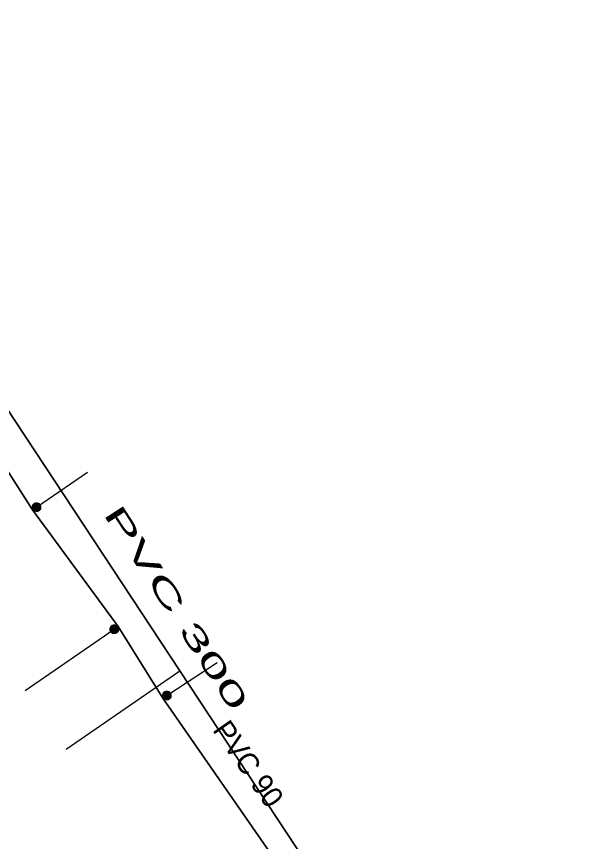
# Model space of a CAD drawing. Extents: x -873619 to -867639, y -1015082 to -1012326.
# Drawn here: x -867939.32 to -867910.18, y -1012859.98 to -1012817 of the extents above; entities that cross this region are included whole.
import ezdxf

# ---------------------------------------------------------------- set-up
doc = ezdxf.new("R2010")
doc.units = 0
doc.header["$LTSCALE"] = 0.44
for name, color, linetype, lineweight in [('1', 7, 'Continuous', 13), ('12', 7, 'Continuous', 13), ('21', 7, 'Continuous', 35), ('23', 7, 'Continuous', 25), ('3', 7, 'Continuous', 25)]:
    doc.layers.add(name, color=color, linetype=linetype, lineweight=lineweight)

msp = doc.modelspace()

# ---------------------------------------------------------------- linework, layer by layer
at = {"layer": '1', "lineweight": 35}
msp.add_lwpolyline([(-867979.181, -1012799.683), (-867972.83, -1012801.89), (-867965.59, -1012804.78), (-867963.787, -1012807.409), (-867948.768, -1012827.087), (-867948.538, -1012827.407), (-867943.513, -1012834.828), (-867938.476, -1012842.701), (-867934.013, -1012848.778), (-867931.689, -1012852.506), (-867924.702, -1012862.569), (-867923.496, -1012864.901), (-867916.531, -1012874.592), (-867908.231, -1012887.091), (-867905.717, -1012890.99), (-867899.122, -1012900.29), (-867892.55, -1012910.082), (-867889.71, -1012914.412), (-867888.18, -1012916.7), (-867891.84, -1012919), (-867886.89, -1012927.31), (-867886.728, -1012931.158)], dxfattribs=at)
at = {"layer": '12'}
for points in [[(-867938.039, -1012842.56), (-867938.045, -1012842.508), (-867938.062, -1012842.458), (-867938.091, -1012842.414), (-867938.128, -1012842.377), (-867938.173, -1012842.35), (-867938.223, -1012842.333), (-867938.276, -1012842.329), (-867938.328, -1012842.336), (-867938.377, -1012842.355), (-867938.42, -1012842.384), (-867938.456, -1012842.423), (-867938.482, -1012842.468), (-867938.498, -1012842.519), (-867938.501, -1012842.571), (-867938.493, -1012842.623), (-867938.473, -1012842.672), (-867938.442, -1012842.715), (-867938.403, -1012842.749), (-867938.357, -1012842.775), (-867938.306, -1012842.789), (-867938.253, -1012842.791), (-867938.202, -1012842.781), (-867938.154, -1012842.76), (-867938.111, -1012842.729), (-867938.077, -1012842.688), (-867938.053, -1012842.642), (-867938.041, -1012842.591)], [(-867938.069, -1012842.56), (-867938.075, -1012842.511), (-867938.092, -1012842.465), (-867938.12, -1012842.425), (-867938.157, -1012842.393), (-867938.201, -1012842.371), (-867938.249, -1012842.36), (-867938.298, -1012842.36), (-867938.345, -1012842.373), (-867938.388, -1012842.397), (-867938.424, -1012842.43), (-867938.451, -1012842.471), (-867938.467, -1012842.518), (-867938.471, -1012842.567), (-867938.464, -1012842.615), (-867938.445, -1012842.66), (-867938.415, -1012842.7), (-867938.377, -1012842.731), (-867938.333, -1012842.751), (-867938.285, -1012842.761), (-867938.236, -1012842.759), (-867938.189, -1012842.744), (-867938.146, -1012842.719), (-867938.112, -1012842.685), (-867938.086, -1012842.643), (-867938.072, -1012842.596)], [(-867938.099, -1012842.56), (-867938.105, -1012842.515), (-867938.122, -1012842.473), (-867938.15, -1012842.438), (-867938.186, -1012842.411), (-867938.228, -1012842.394), (-867938.273, -1012842.389), (-867938.318, -1012842.395), (-867938.359, -1012842.414), (-867938.394, -1012842.442), (-867938.421, -1012842.479), (-867938.437, -1012842.521), (-867938.441, -1012842.566), (-867938.434, -1012842.611), (-867938.415, -1012842.652), (-867938.386, -1012842.686), (-867938.349, -1012842.712), (-867938.306, -1012842.728), (-867938.261, -1012842.731), (-867938.216, -1012842.723), (-867938.176, -1012842.703), (-867938.142, -1012842.674), (-867938.116, -1012842.636), (-867938.102, -1012842.593)], [(-867938.129, -1012842.56), (-867938.134, -1012842.519), (-867938.152, -1012842.482), (-867938.179, -1012842.451), (-867938.214, -1012842.43), (-867938.254, -1012842.419), (-867938.295, -1012842.421), (-867938.334, -1012842.434), (-867938.368, -1012842.458), (-867938.393, -1012842.49), (-867938.408, -1012842.528), (-867938.411, -1012842.569), (-867938.403, -1012842.609), (-867938.383, -1012842.645), (-867938.354, -1012842.674), (-867938.317, -1012842.693), (-867938.277, -1012842.701), (-867938.236, -1012842.697), (-867938.198, -1012842.682), (-867938.166, -1012842.656), (-867938.143, -1012842.622), (-867938.13, -1012842.583)], [(-867938.159, -1012842.56), (-867938.164, -1012842.524), (-867938.182, -1012842.492), (-867938.208, -1012842.467), (-867938.242, -1012842.452), (-867938.278, -1012842.449), (-867938.313, -1012842.457), (-867938.344, -1012842.477), (-867938.367, -1012842.505), (-867938.38, -1012842.539), (-867938.38, -1012842.576), (-867938.369, -1012842.611), (-867938.348, -1012842.64), (-867938.318, -1012842.661), (-867938.283, -1012842.671), (-867938.246, -1012842.669), (-867938.212, -1012842.655), (-867938.185, -1012842.632), (-867938.166, -1012842.6), (-867938.159, -1012842.565)], [(-867938.189, -1012842.56), (-867938.194, -1012842.529), (-867938.211, -1012842.503), (-867938.237, -1012842.486), (-867938.267, -1012842.479), (-867938.298, -1012842.483), (-867938.325, -1012842.5), (-867938.343, -1012842.524), (-867938.351, -1012842.555), (-867938.347, -1012842.585), (-867938.332, -1012842.613), (-867938.308, -1012842.632), (-867938.278, -1012842.641), (-867938.247, -1012842.638), (-867938.219, -1012842.624), (-867938.199, -1012842.6), (-867938.189, -1012842.571)], [(-867938.219, -1012842.56), (-867938.224, -1012842.536), (-867938.241, -1012842.518), (-867938.264, -1012842.509), (-867938.288, -1012842.512), (-867938.309, -1012842.526), (-867938.32, -1012842.548), (-867938.32, -1012842.573), (-867938.308, -1012842.594), (-867938.288, -1012842.608), (-867938.263, -1012842.611), (-867938.24, -1012842.602), (-867938.224, -1012842.584)], [(-867938.249, -1012842.56), (-867938.254, -1012842.545), (-867938.269, -1012842.539), (-867938.284, -1012842.543), (-867938.291, -1012842.557), (-867938.287, -1012842.572), (-867938.274, -1012842.581), (-867938.259, -1012842.578), (-867938.249, -1012842.566)], [(-867933.989, -1012848.92), (-867933.995, -1012848.868), (-867934.012, -1012848.818), (-867934.041, -1012848.774), (-867934.078, -1012848.737), (-867934.123, -1012848.71), (-867934.173, -1012848.693), (-867934.226, -1012848.689), (-867934.277, -1012848.696), (-867934.326, -1012848.715), (-867934.37, -1012848.744), (-867934.406, -1012848.783), (-867934.432, -1012848.828), (-867934.448, -1012848.879), (-867934.451, -1012848.931), (-867934.443, -1012848.983), (-867934.423, -1012849.032), (-867934.392, -1012849.075), (-867934.353, -1012849.109), (-867934.307, -1012849.135), (-867934.255, -1012849.149), (-867934.203, -1012849.151), (-867934.152, -1012849.141), (-867934.103, -1012849.12), (-867934.061, -1012849.089), (-867934.027, -1012849.048), (-867934.003, -1012849.002), (-867933.99, -1012848.951)], [(-867934.019, -1012848.92), (-867934.025, -1012848.871), (-867934.042, -1012848.825), (-867934.07, -1012848.785), (-867934.107, -1012848.753), (-867934.151, -1012848.731), (-867934.199, -1012848.72), (-867934.248, -1012848.72), (-867934.294, -1012848.733), (-867934.338, -1012848.757), (-867934.374, -1012848.79), (-867934.401, -1012848.831), (-867934.417, -1012848.878), (-867934.421, -1012848.927), (-867934.414, -1012848.975), (-867934.395, -1012849.02), (-867934.365, -1012849.06), (-867934.326, -1012849.091), (-867934.282, -1012849.111), (-867934.235, -1012849.121), (-867934.186, -1012849.119), (-867934.139, -1012849.104), (-867934.096, -1012849.079), (-867934.061, -1012849.045), (-867934.036, -1012849.003), (-867934.022, -1012848.956)], [(-867934.049, -1012848.92), (-867934.054, -1012848.875), (-867934.071, -1012848.833), (-867934.1, -1012848.798), (-867934.136, -1012848.771), (-867934.178, -1012848.754), (-867934.223, -1012848.749), (-867934.267, -1012848.755), (-867934.309, -1012848.774), (-867934.343, -1012848.802), (-867934.37, -1012848.839), (-867934.387, -1012848.881), (-867934.391, -1012848.926), (-867934.384, -1012848.971), (-867934.365, -1012849.012), (-867934.336, -1012849.046), (-867934.299, -1012849.072), (-867934.255, -1012849.088), (-867934.211, -1012849.091), (-867934.166, -1012849.083), (-867934.125, -1012849.063), (-867934.092, -1012849.034), (-867934.066, -1012848.996), (-867934.052, -1012848.953)], [(-867934.079, -1012848.92), (-867934.083, -1012848.879), (-867934.102, -1012848.842), (-867934.129, -1012848.811), (-867934.164, -1012848.79), (-867934.204, -1012848.779), (-867934.245, -1012848.781), (-867934.284, -1012848.794), (-867934.318, -1012848.818), (-867934.343, -1012848.85), (-867934.358, -1012848.888), (-867934.36, -1012848.929), (-867934.353, -1012848.969), (-867934.333, -1012849.005), (-867934.304, -1012849.034), (-867934.267, -1012849.053), (-867934.227, -1012849.061), (-867934.186, -1012849.057), (-867934.147, -1012849.042), (-867934.115, -1012849.016), (-867934.093, -1012848.982), (-867934.08, -1012848.943)], [(-867934.108, -1012848.92), (-867934.114, -1012848.884), (-867934.132, -1012848.852), (-867934.157, -1012848.827), (-867934.191, -1012848.812), (-867934.228, -1012848.809), (-867934.262, -1012848.817), (-867934.294, -1012848.837), (-867934.316, -1012848.865), (-867934.33, -1012848.899), (-867934.33, -1012848.936), (-867934.319, -1012848.971), (-867934.298, -1012849), (-867934.267, -1012849.021), (-867934.233, -1012849.031), (-867934.196, -1012849.029), (-867934.162, -1012849.015), (-867934.135, -1012848.992), (-867934.115, -1012848.96), (-867934.108, -1012848.925)], [(-867934.139, -1012848.92), (-867934.144, -1012848.889), (-867934.161, -1012848.863), (-867934.186, -1012848.846), (-867934.217, -1012848.839), (-867934.248, -1012848.843), (-867934.275, -1012848.86), (-867934.293, -1012848.884), (-867934.301, -1012848.915), (-867934.297, -1012848.945), (-867934.282, -1012848.973), (-867934.257, -1012848.992), (-867934.228, -1012849.001), (-867934.196, -1012848.998), (-867934.169, -1012848.984), (-867934.149, -1012848.96), (-867934.139, -1012848.931)], [(-867934.169, -1012848.92), (-867934.174, -1012848.896), (-867934.191, -1012848.878), (-867934.213, -1012848.869), (-867934.238, -1012848.872), (-867934.259, -1012848.886), (-867934.27, -1012848.908), (-867934.27, -1012848.933), (-867934.257, -1012848.954), (-867934.238, -1012848.968), (-867934.213, -1012848.971), (-867934.19, -1012848.962), (-867934.174, -1012848.944)], [(-867934.199, -1012848.92), (-867934.204, -1012848.905), (-867934.218, -1012848.899), (-867934.233, -1012848.903), (-867934.24, -1012848.917), (-867934.237, -1012848.932), (-867934.223, -1012848.941), (-867934.208, -1012848.938), (-867934.199, -1012848.926)], [(-867931.249, -1012852.37), (-867931.255, -1012852.318), (-867931.272, -1012852.268), (-867931.301, -1012852.224), (-867931.338, -1012852.187), (-867931.383, -1012852.16), (-867931.433, -1012852.143), (-867931.486, -1012852.139), (-867931.538, -1012852.146), (-867931.587, -1012852.165), (-867931.63, -1012852.194), (-867931.666, -1012852.233), (-867931.692, -1012852.278), (-867931.708, -1012852.329), (-867931.711, -1012852.381), (-867931.703, -1012852.433), (-867931.683, -1012852.482), (-867931.652, -1012852.525), (-867931.613, -1012852.559), (-867931.567, -1012852.585), (-867931.516, -1012852.599), (-867931.463, -1012852.601), (-867931.412, -1012852.591), (-867931.364, -1012852.57), (-867931.321, -1012852.539), (-867931.287, -1012852.498), (-867931.263, -1012852.452), (-867931.25, -1012852.401)], [(-867931.279, -1012852.37), (-867931.285, -1012852.321), (-867931.302, -1012852.275), (-867931.33, -1012852.235), (-867931.367, -1012852.203), (-867931.411, -1012852.181), (-867931.459, -1012852.17), (-867931.508, -1012852.17), (-867931.554, -1012852.183), (-867931.598, -1012852.207), (-867931.634, -1012852.24), (-867931.661, -1012852.281), (-867931.677, -1012852.328), (-867931.681, -1012852.377), (-867931.674, -1012852.425), (-867931.655, -1012852.47), (-867931.625, -1012852.51), (-867931.587, -1012852.541), (-867931.543, -1012852.561), (-867931.495, -1012852.571), (-867931.446, -1012852.569), (-867931.399, -1012852.554), (-867931.356, -1012852.529), (-867931.321, -1012852.495), (-867931.296, -1012852.453), (-867931.282, -1012852.406)], [(-867931.309, -1012852.37), (-867931.315, -1012852.325), (-867931.331, -1012852.283), (-867931.36, -1012852.248), (-867931.396, -1012852.221), (-867931.438, -1012852.204), (-867931.483, -1012852.199), (-867931.527, -1012852.205), (-867931.569, -1012852.224), (-867931.603, -1012852.252), (-867931.63, -1012852.289), (-867931.647, -1012852.331), (-867931.651, -1012852.376), (-867931.644, -1012852.421), (-867931.625, -1012852.462), (-867931.596, -1012852.496), (-867931.559, -1012852.522), (-867931.516, -1012852.538), (-867931.471, -1012852.541), (-867931.426, -1012852.533), (-867931.386, -1012852.513), (-867931.352, -1012852.484), (-867931.326, -1012852.446), (-867931.312, -1012852.403)], [(-867931.339, -1012852.37), (-867931.343, -1012852.329), (-867931.362, -1012852.292), (-867931.389, -1012852.261), (-867931.424, -1012852.24), (-867931.464, -1012852.229), (-867931.505, -1012852.231), (-867931.544, -1012852.244), (-867931.578, -1012852.268), (-867931.603, -1012852.3), (-867931.618, -1012852.338), (-867931.62, -1012852.379), (-867931.613, -1012852.419), (-867931.593, -1012852.455), (-867931.564, -1012852.484), (-867931.527, -1012852.503), (-867931.487, -1012852.511), (-867931.446, -1012852.507), (-867931.407, -1012852.492), (-867931.375, -1012852.466), (-867931.353, -1012852.432), (-867931.34, -1012852.393)], [(-867931.369, -1012852.37), (-867931.374, -1012852.334), (-867931.392, -1012852.302), (-867931.418, -1012852.277), (-867931.451, -1012852.262), (-867931.488, -1012852.259), (-867931.522, -1012852.267), (-867931.554, -1012852.287), (-867931.576, -1012852.315), (-867931.59, -1012852.349), (-867931.59, -1012852.386), (-867931.579, -1012852.421), (-867931.558, -1012852.45), (-867931.527, -1012852.471), (-867931.493, -1012852.481), (-867931.456, -1012852.479), (-867931.422, -1012852.465), (-867931.395, -1012852.442), (-867931.375, -1012852.41), (-867931.369, -1012852.375)], [(-867931.399, -1012852.37), (-867931.404, -1012852.339), (-867931.421, -1012852.313), (-867931.446, -1012852.296), (-867931.477, -1012852.289), (-867931.508, -1012852.293), (-867931.535, -1012852.31), (-867931.553, -1012852.334), (-867931.561, -1012852.365), (-867931.557, -1012852.395), (-867931.542, -1012852.423), (-867931.517, -1012852.442), (-867931.488, -1012852.451), (-867931.456, -1012852.448), (-867931.429, -1012852.434), (-867931.409, -1012852.41), (-867931.399, -1012852.381)], [(-867931.429, -1012852.37), (-867931.434, -1012852.346), (-867931.451, -1012852.328), (-867931.473, -1012852.319), (-867931.498, -1012852.322), (-867931.519, -1012852.336), (-867931.53, -1012852.358), (-867931.53, -1012852.383), (-867931.517, -1012852.404), (-867931.498, -1012852.418), (-867931.473, -1012852.421), (-867931.45, -1012852.412), (-867931.434, -1012852.394)], [(-867931.459, -1012852.37), (-867931.464, -1012852.355), (-867931.478, -1012852.349), (-867931.494, -1012852.353), (-867931.5, -1012852.367), (-867931.497, -1012852.382), (-867931.483, -1012852.391), (-867931.468, -1012852.388), (-867931.459, -1012852.376)]]:
    msp.add_lwpolyline(points, close=True, dxfattribs=at)
at = {"layer": '21'}
msp.add_line((-867952.038, -1012818.911), (-867915.289, -1012874.6), dxfattribs=at)
at = {"layer": '23'}
msp.add_line((-867930.8, -1012851.108), (-867936.73, -1012855.19), dxfattribs=at)
at = {"layer": '3'}
for points in [[(-867938.476, -1012842.701), (-867938.27, -1012842.56), (-867935.623, -1012840.741)], [(-867938.868, -1012852.108), (-867934.22, -1012848.92), (-867934.013, -1012848.778)], [(-867931.689, -1012852.506), (-867931.48, -1012852.37), (-867928.86, -1012850.656)]]:
    msp.add_lwpolyline(points, dxfattribs=at)

# ---------------------------------------------------------------- texts
at = {"layer": '1', "width": 2.1}
msp.add_text('PVC 300 ', height=1.1, rotation=303, dxfattribs=at).set_placement((-867934.824, -1012842.908))
at = {"layer": '1'}
msp.add_text('PVC 90', height=1.1, rotation=305, dxfattribs=at).set_placement((-867929.132, -1012854.17))

doc.saveas('drawing.dxf')
